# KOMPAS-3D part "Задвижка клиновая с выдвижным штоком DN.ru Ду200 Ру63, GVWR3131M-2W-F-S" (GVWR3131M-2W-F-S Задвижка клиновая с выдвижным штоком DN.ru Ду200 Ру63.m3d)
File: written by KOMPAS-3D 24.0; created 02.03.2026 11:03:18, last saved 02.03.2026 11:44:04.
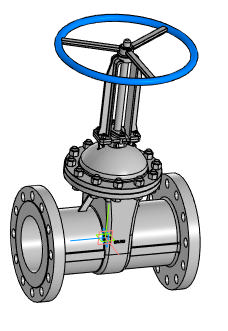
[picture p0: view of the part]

Document properties: Автор: R2D2; Полное имя файла: GVWR3131M-2W-F-S Задвижка клиновая с выдвижным штоком DN.ru Ду200 Ру63.cdw

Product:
- Part/product: Задвижка клиновая с выдвижным штоком DN.ru Ду200 Ру63  | designation GVWR3131M-2W-F-S
    Масса: 209
    Раздел спецификации: Прочие изделия
    Форматы листов документа: A2
    Примечание: D040-07397
    additional columns: D040-07397

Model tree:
1. Операция без истории:2
2. Скругление:3  (with: Ребро.Операция без истории:2)
     Радиус = 8

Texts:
  GVWR3131M-2W-F-S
